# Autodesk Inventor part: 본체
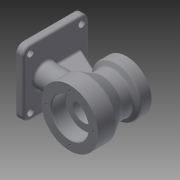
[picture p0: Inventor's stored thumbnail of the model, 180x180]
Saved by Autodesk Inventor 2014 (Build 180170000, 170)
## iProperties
Created: 2019-01
Part Number: 본체
Material: Generic
Document SubType Name: Modeling
Designer: kh
Density: 1 g/cm^3
Appearance: Default
Author: kh
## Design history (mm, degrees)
sketch "스케치3"
  geometry: L1 (0, 0)-(80, 0); L2 (0, 0)-(0, 40); L3 (0, 40)-(25, 40); L4 (25, 40)-(45.785, 28); L5 (45.785, 28)-(60.959, 28); L6 (60.959, 28)-(65, 35); L7 (65, 35)-(80, 35); L8 (80, 35)-(80, 0); L9 (0, 26)-(20, 26); L10 (20, 26)-(20, 16); L11 (20, 16)-(63, 16); L12 (63, 16)-(63, 20); L13 (63, 20)-(80, 20)
  constraints: 26 end point, 9 perpendicular, 2 parallel, 2 point on line, 1 horizontal
  dimensions: "d10" = 80 distance of L1.start L1.end; "d12" = 25 distance of L2.end L3.end; "d13" = 15 distance of L6.end L7.end; "d17" = 70 diameter of L7 L1; "d19" = 52 diameter of L9 L1; "d22" = 32 diameter of L11 L1; "d23" = 20 distance of L9.start L9.end; "d24" = 17 distance of L12.end L13.end; "d25" = 40 diameter of L13 L1; "d26" = 56 diameter of L5 L1; "d27" = 80 diameter of L3 L1; "d28" = 30 deg angle of L5 L4
revolve "회전1" sketch "스케치3" stored, may be unused: angle "d29" = 90 deg
node "작업 평면3"
sketch "스케치4"
  geometry: L1 (0, 0)-(5, 0); L2 (5, 46)-(97, 46); L3 (97, 46)-(97, -46); L4 (97, -46)-(5, -46); L5 (5, -46)-(5, 46); L6 (5, 46)-(97, -46); L7 (97, 46)-(5, -46); 1 further point
  constraints: 14 end point, 3 midpoint, 2 horizontal, 2 parallel, 1 perpendicular
  dimensions: "d31" = 5 distance of L1.end L1.start; "d32" = 92 distance of L2.start L2.end; "d33" = 92 distance of L2.end L3.end
extrude "돌출3" join sketch "스케치4" distance "d34" = 10; taper "d35" = 0 deg
sketch "스케치5"
  geometry: L1 (-46, 5)-(46, 5) reference; L2 (46, 97)-(-46, 97) reference; L3 (0, 5)-(0, 35); C1 r 16 at (0, 35); 1 further point
  constraints: 2 end point, 1 centre point, 1 coincident, 1 midpoint, 1 perpendicular
  dimensions: "d36" = 30 distance of L3.start L3.end; "d37" = 32 diameter of C1
extrude "돌출4" join sketch "스케치5" stored distance "d38" = 10; taper "d39" = 0 deg
sketch "스케치6"
  geometry: L1 (-80, 97)-(-80, 5) reference; L2 (-80, 97)-(-70, 97) reference; L3 (-70, 5)-(-70, 97) reference; L4 (-80, 5)-(-70, 5) reference; L5 (-70, 87)-(-45.508, 75.579); 1 further point
  constraints: 2 end point, 1 point on line
  dimensions: "d40" = 10 distance of L2.end L5.start; "d41" = 25 deg angle of L2 L5
feature "리브1" sketch "스케치6" dims "d42" = 1, "d43" = 10, "d44" = 0, "d45" = 0, "d46" = 1, "d47" = 1
fillet "모깎기1" dims "d48" = 10
hole "구멍1" diameter "d51" = 9; stored, may be unused: countersink angle "d55" = 90 deg, drill point angle "d57" = 118 deg; dims "d49" = 10, "d50" = 10, "d52" = 6, "d53" = 4, "d54" = 2, "d56" = 8
hole "구멍2" diameter "d60" = 9; stored, may be unused: countersink angle "d64" = 90 deg, drill point angle "d66" = 118 deg; dims "d58" = 10, "d59" = 10, "d61" = 6, "d62" = 4, "d63" = 2, "d65" = 8
hole "구멍3" diameter "d69" = 9; stored, may be unused: countersink angle "d73" = 90 deg, drill point angle "d75" = 118 deg; dims "d67" = 10, "d68" = 10, "d70" = 6, "d71" = 4, "d72" = 2, "d74" = 8
hole "구멍4" diameter "d78" = 9; stored, may be unused: countersink angle "d82" = 90 deg, drill point angle "d84" = 118 deg; dims "d76" = 10, "d77" = 10, "d79" = 6, "d80" = 4, "d81" = 2, "d83" = 8
node "작업 평면4"
fillet "모깎기2" dims "d89" = 3
fillet "모깎기3" dims "d90" = 3
fillet "모깎기4" dims "d91" = 3
fillet "모깎기5" dims "d92" = 0.6
fillet "모깎기6" dims "d93" = 1
chamfer "모따기1" distance "d94" = 1; stored, may be unused: second distance "d95" = 2, angle "d96" = 45 deg
node "작업 평면5"
sketch "스케치8"
  geometry: L1 (-5.947, 22.076)-(-5.992, 49.917); L2 (-5.992, 49.917)-(-2.053, 49.924); L3 (-2.053, 49.924)-(-2.008, 22.083); L4 (-2.008, 22.083)-(-5.947, 22.076); L5 (-2.008, 22.083)-(-5.992, 49.917); L6 (-7, -10)-(0, -10) reference; L7 (0, -10)-(-4, -10); L8 (-4, -10)-(-4, 36); 1 further point
  constraints: 6 end point, 1 midpoint, 1 point on line, 1 vertical, 2 other
  dimensions: "d98" = 4 distance of L6.end L7.end; "d99" = 46 distance of L8.end L7.end
feature "엠보싱2" sketch "스케치8" dims "d10" = 80, "d12" = 25, "d13" = 15, "d17" = 70, "d19" = 52, "d22" = 32, "d23" = 20, "d24" = 17, "d25" = 40, "d26" = 56, "d27" = 80, "d28" = 30 deg, "d31" = 5, "d32" = 92, "d33" = 92, "d100" = 0.5, "d101" = 0
sketch "스케치9" dims "d102" = 66
  geometry: L1 (0, 0)-(33, 0); C1 r 27 at (0, 0) reference; 1 further point
  constraints: 2 coincident, 2 end point, 1 horizontal, 1 horizontal alignment, 2 other
hole "구멍5" sketch "스케치9" at (33, 0) diameter "d103" = 3.242; stored, may be unused: countersink angle "d107" = 90 deg, drill point angle "d109" = 118 deg; dims "d104" = 9, "d105" = 4, "d106" = 2, "d108" = 11
sketch "스케치10" dims "d113" = 55
  geometry: L1 (0, 0)-(27.5, 0); C1 r 21 at (0, 0) reference; 1 further point
  constraints: 2 coincident, 2 end point, 1 horizontal, 1 horizontal alignment, 2 other
hole "구멍6" sketch "스케치10" at (27.5, 0) diameter "d114" = 3.242; stored, may be unused: countersink angle "d118" = 90 deg, drill point angle "d120" = 118 deg; dims "d115" = 9, "d116" = 4, "d117" = 2, "d119" = 11
node "솔리드2"
pattern_circular "원형 패턴1" dims angle "d111" = 360 deg
pattern_circular "원형 패턴2" dims angle "d122" = 360 deg
node "투영된 루프2"
other parameters: "d85" = 12, "d97" = 9.25
